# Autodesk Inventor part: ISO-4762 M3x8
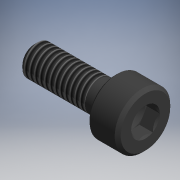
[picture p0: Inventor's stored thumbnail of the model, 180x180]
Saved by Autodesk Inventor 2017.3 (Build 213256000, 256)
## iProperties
Part Number: ISO-4762 M3x8
Material: Generic
Catalog Web Link: www.cadenas.de
Description: ISO-4762-Cylinder head screws cap screws
Vendor: FESTO
Document SubType Name: Modeling
Designer: partserver
Manufacturer: FESTO
Mass: 0.118757 g
Surface Area: 1.77239 cm^2
Volume: 0.118757 cm^3
Density: 1 g/cm^3
Appearance: PSOLRGB-80-80-80
Category: PARTsolutions
Company: FESTO
Title: ISO-4762 M3x8
Author: Cadenas PARTsolutions
Comments: Cylinder head screws cap screws
PSOL_IDENT_0: {$CADENAS_DATA\23d-libs\festo\zyl_zubeh\din_4762\din_en_iso_4762.prj},182 {VTYP=3D},{NB=ISO-4762 M3x
PSOL_IDENT_1: 8},{LINA=ISO-4762 M3x8},{NN=ISO-4762},{DATE=19.05.2020 13:42:07},{GEOMDATE=17.07.2018 07:56:43},{VER
PSOL_IDENT_2: SION=v080331135824},{LINEID=300},{WBVAR=},{WBNUMERIC=}  {NB=ISO-4762 M3x8},{LINA=ISO-4762 M3x8},{KT=
PSOL_IDENT_3: DUMMY},{IDNR=},{D=3.000},{D3=2.387},{P=0.500},{L=8.000},{B=6.5},{BX=18.000},{LS=0},{LG=1.5},{DK=5.50
PSOL_IDENT_4: 0},{DA=3.600},{DS=3.000},{E=2.870},{LF=0.510},{K=3.000},{R=0.100},{S=2.500},{T=1.300},{V=0.300},{DW=
PSOL_IDENT_5: 5.070},{W=1.150},{NENN=M3x8}
NB: ISO-4762 M3x8
NN: ISO-4762
NT: Cylinder head screws cap screws
NBSYN: ISO-4762 $NENN.
LINA: ISO-4762 M3x8
CATALOG: Festo
ROWDESC: M3x8
D: 3
D3: 2.387
P: 0.5
L: 8
B: 6.5
LS: 0
LG: 1.5
DK: 5.5
DA: 3.6
DS: 3
E: 2.87
LF: 0.51
K: 3
R: 0.1
S: 2.5
T: 1.3
V: 0.3
DW: 5.07
W: 1.15
SUPPLIER: FESTO
ARTICLENO: ISO-4762 M3x8
BOMINFO: ISO-4762 M3x8
CREATOR: CADENAS GmbH
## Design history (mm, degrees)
sketch "Sketch_1"
  geometry: L1 (8, 0)-(-3, 0); L2 (-3, 0)-(-3, 2.75); L3 (-3, 2.75)-(0, 2.75); L4 (0, 2.75)-(0, 1.8); L5 (0, 1.8)-(0.51, 1.5); L6 (0.51, 1.5)-(7.694, 1.5); L7 (7.694, 1.5)-(8, 1.194); L8 (8, 1.194)-(8, 0); L9 (8, 0)-(-3, 0)
  constraints: 18 end point
revolve "Revolution1" sketch "Sketch_1" stored, may be unused: angle "d0" = 360 deg
thread "Thread1" dims "d1" = 6.1935, "d2" = 0
sketch "Sketch_6"
  geometry: L1 (0, 0)-(-3, 0); L2 (-3, 3.3)-(-3, 2.45); L3 (-3, 2.45)-(-2.7, 2.75); L4 (-2.7, 2.75)-(-0.215, 2.75); L5 (-0.215, 2.75)-(0, 2.535); L6 (0, 2.535)-(0, 3.3); L7 (0, 3.3)-(-3, 3.3)
  constraints: 14 end point
revolve "Revolution2" sketch "Sketch_6" stored, may be unused: angle "d3" = 360 deg
sketch "Sketch3"
  geometry: 1 further point
hole "Hole1" sketch "Sketch3" at (0, 0) diameter "d4" = 2.5; stored, may be unused: countersink angle "d8" = 90 deg, drill point angle "d10" = 120 deg; dims "d5" = 6, "d6" = 2.85, "d7" = 2, "d9" = 1.3
sketch "Sketch_2"
  geometry: L1 (-1.25, -0.722)-(0, -1.443); L2 (0, -1.443)-(1.25, -0.722); L3 (1.25, -0.722)-(1.25, 0.722); L4 (1.25, 0.722)-(0, 1.443); L5 (0, 1.443)-(-1.25, 0.722); L6 (-1.25, 0.722)-(-1.25, -0.722)
  constraints: 12 end point
extrude "Extrusion1" cut sketch "Sketch_2" stored distance "d11" = 2.6; taper "d12" = 0 deg
node "ANBAU_XY"
node "ANBAU_YZ"
node "ANBAU_ZX"
node "ANBAU_X"
node "ANBAU_Y"
node "ANBAU_Z"
node "ANBAU_Center"
node "IP1_XY"
node "IP1_YZ"
node "IP1_ZX"
node "IP1_X"
node "IP1_Y"
node "IP1_Z"
node "IP1_Center"
node "IP2_XY"
node "IP2_YZ"
node "IP2_ZX"
node "IP2_X"
node "IP2_Y"
node "IP2_Z"
node "IP2_Center"
node "IP3_XY"
node "IP3_YZ"
node "IP3_ZX"
node "IP3_X"
node "IP3_Y"
node "IP3_Z"
node "IP3_Center"
body "Solid1"
other parameters: "d13" = 0, "d14" = 0, "d15" = 0, "d16" = 0
